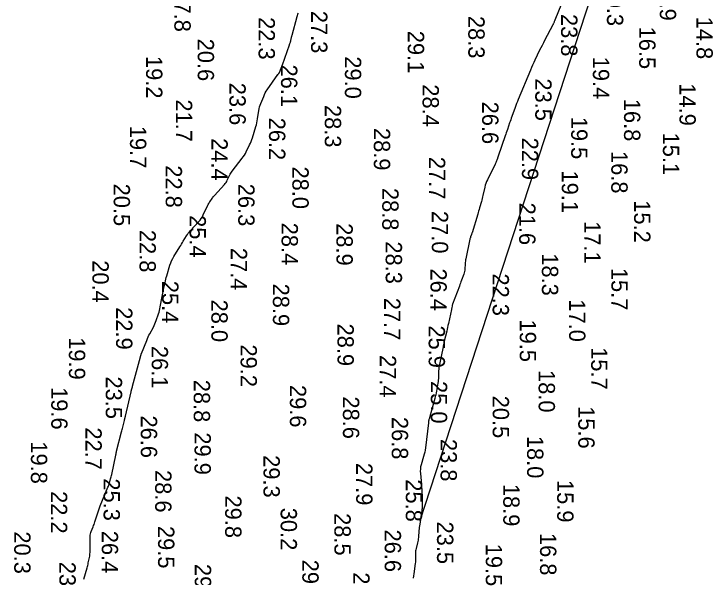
# Model space of a CAD drawing. Extents: x 1178573 to 1187098, y 693282 to 751751.
# Drawn here: x 1178579 to 1179114, y 717678 to 718109 of the extents above; entities that cross this region are included whole.
import ezdxf

# ---------------------------------------------------------------- set-up
doc = ezdxf.new("R2010")
doc.units = 0
for name, color, linetype in [('G-ANNO-PATT', 7, 'Continuous'), ('V-HYDS-MAJR', 7, 'Continuous'), ('V-HYDS-SOUN', 7, 'Continuous')]:
    doc.layers.add(name, color=color, linetype=linetype)

msp = doc.modelspace()

# ---------------------------------------------------------------- linework, layer by layer
at = {"layer": 'G-ANNO-PATT'}
msp.add_line((1178890.09, 717721.65), (1179089.95, 718334.23), dxfattribs=at)
msp.add_lwpolyline([(1178998.18, 718116.98), (1178993.14, 718104.59), (1178993.09, 718104.45), (1178993.04, 718104.32), (1178992.99, 718104.19), (1178992.94, 718104.05), (1178992.76, 718103.52), (1178992.72, 718103.38), (1178992.67, 718103.25), (1178992.61, 718103.12), (1178992.56, 718102.99), (1178992.1, 718101.97), (1178992.01, 718101.76), (1178991.91, 718101.55), (1178991.8, 718101.34), (1178991.7, 718101.14), (1178985.33, 718089.03), (1178984.36, 718087.17), (1178983.41, 718085.31), (1178982.47, 718083.44), (1178981.54, 718081.56), (1178977.87, 718074.03), (1178976.96, 718072.14), (1178976.09, 718070.24), (1178975.25, 718068.33), (1178974.43, 718066.4), (1178965.15, 718043.89), (1178964.53, 718042.36), (1178963.92, 718040.82), (1178963.33, 718039.27), (1178962.75, 718037.72), (1178960.24, 718030.84), (1178959.79, 718029.61), (1178959.35, 718028.38), (1178958.92, 718027.15), (1178958.49, 718025.91), (1178956.8, 718020.96), (1178956.38, 718019.73), (1178955.95, 718018.49), (1178955.53, 718017.25), (1178955.11, 718016.01), (1178949.82, 718000.54), (1178949.76, 718000.34), (1178949.69, 718000.15), (1178949.62, 717999.95), (1178949.55, 717999.76), (1178949.28, 717998.98), (1178949.21, 717998.79), (1178949.14, 717998.59), (1178949.07, 717998.4), (1178949, 717998.21), (1178948.19, 717996.1), (1178948.03, 717995.69), (1178947.86, 717995.28), (1178947.67, 717994.88), (1178947.48, 717994.48), (1178941.47, 717982.4), (1178940.85, 717981.05), (1178940.32, 717979.67), (1178939.87, 717978.26), (1178939.51, 717976.82), (1178938.13, 717970.53), (1178937.85, 717969.31), (1178937.55, 717968.1), (1178937.24, 717966.9), (1178936.9, 717965.69), (1178935.51, 717960.9), (1178935.16, 717959.7), (1178934.81, 717958.51), (1178934.45, 717957.31), (1178934.09, 717956.12), (1178929.75, 717941.91), (1178929.64, 717941.57), (1178929.53, 717941.23), (1178929.42, 717940.89), (1178929.3, 717940.55), (1178928.68, 717938.83), (1178928.63, 717938.67), (1178928.58, 717938.51), (1178928.52, 717938.36), (1178928.47, 717938.2), (1178928.27, 717937.57), (1178928.22, 717937.41), (1178928.18, 717937.25), (1178928.14, 717937.09), (1178928.1, 717936.93), (1178924.99, 717922.01), (1178924.8, 717921.04), (1178924.66, 717920.06), (1178924.55, 717919.08), (1178924.49, 717918.09), (1178924.3, 717914.13), (1178924.22, 717913.15), (1178924.06, 717912.18), (1178923.82, 717911.23), (1178923.51, 717910.3), (1178921.69, 717905.5), (1178921.27, 717904.39), (1178920.85, 717903.28), (1178920.44, 717902.17), (1178920.02, 717901.06), (1178914.84, 717887.22), (1178914.73, 717886.88), (1178914.62, 717886.54), (1178914.54, 717886.2), (1178914.47, 717885.85), (1178914.21, 717884.45), (1178914.15, 717884.1), (1178914.08, 717883.75), (1178914.01, 717883.4), (1178913.94, 717883.05), (1178911.62, 717872.32), (1178911.31, 717870.91), (1178911, 717869.5), (1178910.68, 717868.09), (1178910.35, 717866.68), (1178908.52, 717858.94), (1178908.44, 717858.58), (1178908.36, 717858.22), (1178908.28, 717857.86), (1178908.2, 717857.5), (1178907.89, 717856.06), (1178907.81, 717855.7), (1178907.73, 717855.34), (1178907.66, 717854.98), (1178907.58, 717854.62), (1178904.73, 717841.06), (1178904.51, 717839.89), (1178904.34, 717838.7), (1178904.23, 717837.51), (1178904.18, 717836.31), (1178904.08, 717831.52), (1178904.03, 717830.32), (1178903.93, 717829.13), (1178903.79, 717827.94), (1178903.59, 717826.76), (1178902.47, 717820.68), (1178902.2, 717819.28), (1178901.9, 717817.88), (1178901.57, 717816.49), (1178901.21, 717815.1), (1178897.48, 717801.19), (1178897.4, 717800.91), (1178897.32, 717800.64), (1178897.23, 717800.37), (1178897.14, 717800.09), (1178896.69, 717798.85), (1178896.63, 717798.66), (1178896.58, 717798.46), (1178896.55, 717798.26), (1178896.52, 717798.06), (1178896.46, 717797.26), (1178896.45, 717797.05), (1178896.43, 717796.85), (1178896.41, 717796.65), (1178896.38, 717796.45), (1178894.04, 717777.28), (1178893.8, 717775.62), (1178893.5, 717773.98), (1178893.13, 717772.35), (1178892.69, 717770.74), (1178890.8, 717764.31), (1178890.4, 717762.7), (1178890.17, 717761.07), (1178890.09, 717759.42), (1178890.16, 717757.76), (1178890.96, 717749.32), (1178891.06, 717748.14), (1178891.15, 717746.96), (1178891.24, 717745.78), (1178891.31, 717744.6), (1178891.61, 717739.17), (1178891.65, 717738.34), (1178891.67, 717737.51), (1178891.67, 717736.68), (1178891.66, 717735.85), (1178891.57, 717732.53), (1178891.54, 717731.7), (1178891.48, 717730.87), (1178891.39, 717730.05), (1178891.27, 717729.23), (1178890.09, 717721.65)], dxfattribs=at)
at = {"layer": 'V-HYDS-MAJR'}
for points in [[(1178998.18, 718116.98), (1178993.14, 718104.59), (1178993.09, 718104.45), (1178993.04, 718104.32), (1178992.99, 718104.19), (1178992.94, 718104.05), (1178992.76, 718103.52), (1178992.72, 718103.38), (1178992.67, 718103.25), (1178992.61, 718103.12), (1178992.56, 718102.99), (1178992.1, 718101.97), (1178992.01, 718101.76), (1178991.91, 718101.55), (1178991.8, 718101.34), (1178991.7, 718101.14), (1178985.33, 718089.03), (1178984.36, 718087.17), (1178983.41, 718085.31), (1178982.47, 718083.44), (1178981.54, 718081.56), (1178977.87, 718074.03), (1178976.96, 718072.14), (1178976.09, 718070.24), (1178975.25, 718068.33), (1178974.43, 718066.4), (1178965.15, 718043.89), (1178964.53, 718042.36), (1178963.92, 718040.82), (1178963.33, 718039.27), (1178962.75, 718037.72), (1178960.24, 718030.84), (1178959.79, 718029.61), (1178959.35, 718028.38), (1178958.92, 718027.15), (1178958.49, 718025.91), (1178956.8, 718020.96), (1178956.38, 718019.73), (1178955.95, 718018.49), (1178955.53, 718017.25), (1178955.11, 718016.01), (1178949.82, 718000.54), (1178949.76, 718000.34), (1178949.69, 718000.15), (1178949.62, 717999.95), (1178949.55, 717999.76), (1178949.28, 717998.98), (1178949.21, 717998.79), (1178949.14, 717998.59), (1178949.07, 717998.4), (1178949, 717998.21), (1178948.19, 717996.1), (1178948.03, 717995.69), (1178947.86, 717995.28), (1178947.67, 717994.88), (1178947.48, 717994.48), (1178941.47, 717982.4), (1178940.85, 717981.05), (1178940.32, 717979.67), (1178939.87, 717978.26), (1178939.51, 717976.82), (1178938.13, 717970.53), (1178937.85, 717969.31), (1178937.55, 717968.1), (1178937.24, 717966.9), (1178936.9, 717965.69), (1178935.51, 717960.9), (1178935.16, 717959.7), (1178934.81, 717958.51), (1178934.45, 717957.31), (1178934.09, 717956.12), (1178929.75, 717941.91), (1178929.64, 717941.57), (1178929.53, 717941.23), (1178929.42, 717940.89), (1178929.3, 717940.55), (1178928.68, 717938.83), (1178928.63, 717938.67), (1178928.58, 717938.51), (1178928.52, 717938.36), (1178928.47, 717938.2), (1178928.27, 717937.57), (1178928.22, 717937.41), (1178928.18, 717937.25), (1178928.14, 717937.09), (1178928.1, 717936.93), (1178924.99, 717922.01), (1178924.8, 717921.04), (1178924.66, 717920.06), (1178924.55, 717919.08), (1178924.49, 717918.09), (1178924.3, 717914.13), (1178924.22, 717913.15), (1178924.06, 717912.18), (1178923.82, 717911.23), (1178923.51, 717910.3), (1178921.69, 717905.5), (1178921.27, 717904.39), (1178920.85, 717903.28), (1178920.44, 717902.17), (1178920.02, 717901.06), (1178914.84, 717887.22), (1178914.73, 717886.88), (1178914.62, 717886.54), (1178914.54, 717886.2), (1178914.47, 717885.85), (1178914.21, 717884.45), (1178914.15, 717884.1), (1178914.08, 717883.75), (1178914.01, 717883.4), (1178913.94, 717883.05), (1178911.62, 717872.32), (1178911.31, 717870.91), (1178911, 717869.5), (1178910.68, 717868.09), (1178910.35, 717866.68), (1178908.52, 717858.94), (1178908.44, 717858.58), (1178908.36, 717858.22), (1178908.28, 717857.86), (1178908.2, 717857.5), (1178907.89, 717856.06), (1178907.81, 717855.7), (1178907.73, 717855.34), (1178907.66, 717854.98), (1178907.58, 717854.62), (1178904.73, 717841.06), (1178904.51, 717839.89), (1178904.34, 717838.7), (1178904.23, 717837.51), (1178904.18, 717836.31), (1178904.08, 717831.52), (1178904.03, 717830.32), (1178903.93, 717829.13), (1178903.79, 717827.94), (1178903.59, 717826.76), (1178902.47, 717820.68), (1178902.2, 717819.28), (1178901.9, 717817.88), (1178901.57, 717816.49), (1178901.21, 717815.1), (1178897.48, 717801.19), (1178897.4, 717800.91), (1178897.32, 717800.64), (1178897.23, 717800.37), (1178897.14, 717800.09), (1178896.69, 717798.85), (1178896.63, 717798.66), (1178896.58, 717798.46), (1178896.55, 717798.26), (1178896.52, 717798.06), (1178896.46, 717797.26), (1178896.45, 717797.05), (1178896.43, 717796.85), (1178896.41, 717796.65), (1178896.38, 717796.45), (1178894.04, 717777.28), (1178893.8, 717775.62), (1178893.5, 717773.98), (1178893.13, 717772.35), (1178892.69, 717770.74), (1178890.8, 717764.31), (1178890.4, 717762.7), (1178890.17, 717761.07), (1178890.09, 717759.42), (1178890.16, 717757.76), (1178890.96, 717749.32), (1178891.06, 717748.14), (1178891.15, 717746.96), (1178891.24, 717745.78), (1178891.31, 717744.6), (1178891.61, 717739.17), (1178891.65, 717738.34), (1178891.67, 717737.51), (1178891.67, 717736.68), (1178891.66, 717735.85), (1178891.57, 717732.53), (1178891.54, 717731.7), (1178891.48, 717730.87), (1178891.39, 717730.05), (1178891.27, 717729.23), (1178889.65, 717718.86), (1178889.47, 717717.64), (1178889.31, 717716.41), (1178889.18, 717715.18), (1178889.06, 717713.95), (1178888.62, 717708.64), (1178888.51, 717707.59), (1178888.36, 717706.55), (1178888.16, 717705.52), (1178887.92, 717704.5), (1178886.83, 717700.25), (1178886.62, 717699.31), (1178886.47, 717698.35), (1178886.39, 717697.4), (1178886.37, 717696.43), (1178886.44, 717692.55), (1178886.44, 717691.58), (1178886.4, 717690.61), (1178886.32, 717689.65), (1178886.2, 717688.68), (1178885.11, 717680.89), (1178884.89, 717679.28), (1178884.68, 717677.65)], [(1178632.41, 717676.74), (1178634.88, 717685.4), (1178635.15, 717686.36), (1178635.39, 717687.32), (1178635.62, 717688.28), (1178635.83, 717689.25), (1178636.87, 717694.33), (1178636.94, 717694.7), (1178637, 717695.07), (1178637.05, 717695.45), (1178637.08, 717695.83), (1178637.2, 717697.35), (1178637.22, 717697.72), (1178637.24, 717698.1), (1178637.25, 717698.48), (1178637.25, 717698.86), (1178637.22, 717709.57), (1178637.26, 717710.53), (1178637.4, 717711.48), (1178637.64, 717712.4), (1178637.97, 717713.31), (1178639.48, 717716.9), (1178639.85, 717717.8), (1178640.2, 717718.71), (1178640.54, 717719.62), (1178640.85, 717720.54), (1178644.73, 717732.19), (1178644.75, 717732.25), (1178644.77, 717732.31), (1178644.79, 717732.37), (1178644.82, 717732.43), (1178644.9, 717732.66), (1178644.92, 717732.72), (1178644.94, 717732.78), (1178644.97, 717732.84), (1178644.99, 717732.9), (1178650.89, 717747.08), (1178651.2, 717747.87), (1178651.5, 717748.66), (1178651.77, 717749.47), (1178652.01, 717750.29), (1178652.94, 717753.56), (1178653.17, 717754.38), (1178653.38, 717755.2), (1178653.58, 717756.03), (1178653.76, 717756.86), (1178656.92, 717771.76), (1178656.96, 717771.97), (1178657.01, 717772.18), (1178657.05, 717772.39), (1178657.09, 717772.6), (1178657.28, 717773.7), (1178657.3, 717773.78), (1178657.32, 717773.87), (1178657.34, 717773.96), (1178657.36, 717774.04), (1178657.44, 717774.38), (1178657.46, 717774.47), (1178657.48, 717774.55), (1178657.5, 717774.64), (1178657.52, 717774.72), (1178661.26, 717789.43), (1178661.49, 717790.32), (1178661.71, 717791.21), (1178661.94, 717792.1), (1178662.17, 717792.98), (1178663.51, 717798.21), (1178663.53, 717798.26), (1178663.54, 717798.31), (1178663.55, 717798.36), (1178663.56, 717798.41), (1178663.61, 717798.61), (1178663.62, 717798.66), (1178663.63, 717798.71), (1178663.64, 717798.76), (1178663.66, 717798.81), (1178664.03, 717800.41), (1178664.1, 717800.7), (1178664.16, 717800.98), (1178664.23, 717801.26), (1178664.29, 717801.55), (1178668.53, 717820.09), (1178668.62, 717820.47), (1178668.71, 717820.84), (1178668.82, 717821.22), (1178668.92, 717821.59), (1178669.37, 717823.08), (1178669.47, 717823.45), (1178669.58, 717823.83), (1178669.69, 717824.2), (1178669.79, 717824.58), (1178675.82, 717847.05), (1178675.87, 717847.25), (1178675.93, 717847.46), (1178675.98, 717847.66), (1178676.03, 717847.87), (1178676.25, 717848.69), (1178676.31, 717848.9), (1178676.37, 717849.1), (1178676.44, 717849.3), (1178676.52, 717849.5), (1178680.55, 717859.55), (1178681.09, 717860.85), (1178681.67, 717862.14), (1178682.29, 717863.4), (1178682.93, 717864.65), (1178685.64, 717869.7), (1178686.26, 717870.91), (1178686.83, 717872.14), (1178687.35, 717873.4), (1178687.81, 717874.67), (1178689.59, 717879.83), (1178690, 717881.12), (1178690.37, 717882.43), (1178690.68, 717883.75), (1178690.95, 717885.08), (1178692.36, 717893.06), (1178692.6, 717894.39), (1178692.86, 717895.73), (1178693.13, 717897.05), (1178693.41, 717898.38), (1178694.58, 717903.68), (1178694.89, 717905), (1178695.22, 717906.32), (1178695.57, 717907.63), (1178695.94, 717908.93), (1178698.35, 717917.05), (1178698.93, 717918.81), (1178699.63, 717920.52), (1178700.45, 717922.17), (1178701.38, 717923.78), (1178706.01, 717931.19), (1178706.66, 717932.23), (1178707.3, 717933.28), (1178707.93, 717934.33), (1178708.57, 717935.38), (1178711.08, 717939.6), (1178711.74, 717940.63), (1178712.44, 717941.62), (1178713.21, 717942.58), (1178714.02, 717943.49), (1178720.33, 717950.18), (1178721.39, 717951.4), (1178722.34, 717952.69), (1178723.18, 717954.05), (1178723.91, 717955.48), (1178727.32, 717962.91), (1178727.66, 717963.6), (1178728.02, 717964.28), (1178728.42, 717964.93), (1178728.85, 717965.57), (1178730.61, 717968.1), (1178731.06, 717968.72), (1178731.53, 717969.33), (1178732.02, 717969.92), (1178732.52, 717970.5), (1178740.12, 717978.83), (1178740.76, 717979.58), (1178741.33, 717980.38), (1178741.84, 717981.22), (1178742.29, 717982.11), (1178743.96, 717985.72), (1178744.4, 717986.61), (1178744.89, 717987.47), (1178745.43, 717988.29), (1178746.01, 717989.09), (1178753.69, 717998.93), (1178754.56, 718000.1), (1178755.37, 718001.32), (1178756.12, 718002.58), (1178756.8, 718003.87), (1178759.41, 718009.13), (1178760.03, 718010.46), (1178760.6, 718011.8), (1178761.1, 718013.18), (1178761.55, 718014.57), (1178764.12, 718023.13), (1178764.53, 718024.61), (1178764.9, 718026.1), (1178765.21, 718027.6), (1178765.48, 718029.11), (1178766.45, 718035.36), (1178766.72, 718036.78), (1178767.06, 718038.18), (1178767.49, 718039.55), (1178768, 718040.91), (1178770.18, 718046.28), (1178770.76, 718047.6), (1178771.42, 718048.89), (1178772.14, 718050.13), (1178772.93, 718051.34), (1178781.03, 718062.9), (1178781.13, 718063.04), (1178781.23, 718063.18), (1178781.34, 718063.31), (1178781.44, 718063.44), (1178781.88, 718063.96), (1178781.98, 718064.09), (1178782.07, 718064.23), (1178782.15, 718064.38), (1178782.22, 718064.53), (1178783.55, 718067.98), (1178783.79, 718068.61), (1178784.03, 718069.24), (1178784.26, 718069.88), (1178784.49, 718070.51), (1178789.84, 718085.6), (1178789.94, 718085.88), (1178790.05, 718086.17), (1178790.15, 718086.45), (1178790.26, 718086.74), (1178790.7, 718087.87), (1178790.8, 718088.16), (1178790.89, 718088.45), (1178790.97, 718088.74), (1178791.03, 718089.03), (1178791.45, 718091.26), (1178791.54, 718091.72), (1178791.65, 718092.19), (1178791.76, 718092.65), (1178791.89, 718093.12), (1178795.87, 718107.35), (1178796.14, 718108.23), (1178796.44, 718109.1), (1178796.77, 718109.96)]]:
    msp.add_lwpolyline(points, dxfattribs=at)

# ---------------------------------------------------------------- texts
at = {"layer": 'V-HYDS-SOUN'}
for s, p in [('20.3 ', (1179033.1, 718132.63)), ('16.9 ', (1179073.57, 718136.7)), ('17.8 ', (1178701.75, 718128.17)), ('27.3 ', (1178806.46, 718111.76)), ('22.3 ', (1178766.24, 718106.94)), ('28.3 ', (1178926.9, 718107.86)), ('23.8 ', (1178997.97, 718109.34)), ('14.8 ', (1179101.65, 718107.24)), ('29.1 ', (1178880.56, 718096.47)), ('16.5 ', (1179057.78, 718099.67)), ('20.6 ', (1178719.62, 718090.44)), ('19.2 ', (1178680.07, 718077.18)), ('29.0 ', (1178832.38, 718076.96)), ('19.4 ', (1179022.31, 718076.64)), ('26.1 ', (1178783.44, 718070.65)), ('23.5 ', (1178978.19, 718060.04)), ('23.6 ', (1178743.9, 718056.71)), ('28.4 ', (1178891.86, 718055.51)), ('14.9 ', (1179088.62, 718056.25)), ('21.7 ', (1178702.95, 718043.95)), ('26.6 ', (1178937.5, 718042.24)), ('16.8 ', (1179046.17, 718044.41)), ('28.3 ', (1178816.99, 718039.68)), ('26.2 ', (1178774.24, 718029.97)), ('19.5 ', (1179005.68, 718030.67)), ('19.7 ', (1178667.75, 718023.77)), ('28.9 ', (1178854.54, 718022.1)), ('15.1 ', (1179075.96, 718018.55)), ('24.4 ', (1178730.12, 718014.3)), ('22.9 ', (1178967.99, 718014.72)), ('27.7 ', (1178896.75, 718000.02)), ('16.8 ', (1179036.43, 718004.45)), ('22.8 ', (1178695.12, 717993.52)), ('28.0 ', (1178792.13, 717992.61)), ('19.1 ', (1178998.5, 717989.54)), ('20.5 ', (1178655.26, 717979.49)), ('26.3 ', (1178750.66, 717979.38)), ('28.8 ', (1178861, 717976.2)), ('21.6 ', (1178965.85, 717964.98)), ('15.2 ', (1179053.89, 717966.75)), ('27.0 ', (1178898.95, 717958.59)), ('25.4 ', (1178713.42, 717955.41)), ('28.4 ', (1178783.89, 717949.6)), ('28.9 ', (1178825.9, 717949.23)), ('17.1 ', (1179015.69, 717950.8)), ('22.8 ', (1178675.04, 717944.08)), ('28.3 ', (1178863.61, 717935.29)), ('27.4 ', (1178744.98, 717930.31)), ('18.3 ', (1178983.27, 717926.17)), ('20.4 ', (1178638.98, 717920.83)), ('26.4 ', (1178897.87, 717914.56)), ('15.7 ', (1179036.48, 717915.04)), ('22.3 ', (1178945.54, 717910.75)), ('25.4 ', (1178692.39, 717905.11)), ('28.9 ', (1178777.24, 717902.97)), ('27.7 ', (1178862.37, 717892.11)), ('28.0 ', (1178730.08, 717890.74)), ('17.0 ', (1179004.07, 717890.94)), ('22.9 ', (1178657.1, 717884.93)), ('28.9 ', (1178826.68, 717872.39)), ('25.9 ', (1178896.53, 717870.98)), ('19.5 ', (1178966.31, 717875.52)), ('19.9 ', (1178620.97, 717861.96)), ('26.1 ', (1178684.4, 717855.26)), ('29.2 ', (1178752.48, 717856.41)), ('15.7 ', (1179021, 717854.32)), ('27.4 ', (1178859.12, 717848.29)), ('18.0 ', (1178980.77, 717836.84)), ('23.5 ', (1178649.22, 717831.92)), ('28.8 ', (1178716.58, 717829.38)), ('25.0 ', (1178898.19, 717828.41)), ('19.6 ', (1178607.45, 717823.74)), ('29.6 ', (1178790.22, 717825.38)), ('20.5 ', (1178945.58, 717817.16)), ('28.6 ', (1178830.87, 717816.65)), ('15.6 ', (1179011.15, 717809.17)), ('26.6 ', (1178676.05, 717802.05)), ('26.8 ', (1178868.28, 717800.94)), ('22.7 ', (1178633.6, 717792.93)), ('29.9 ', (1178717.17, 717789.13)), ('18.0 ', (1178971.92, 717786.45)), ('19.8 ', (1178591.87, 717782.24)), ('23.8 ', (1178905.65, 717784.07)), ('29.3 ', (1178770.01, 717771.67)), ('27.9 ', (1178840.99, 717765.77)), ('28.6 ', (1178687.04, 717760.29)), ('25.3 ', (1178647.54, 717753.92)), ('25.8 ', (1178879.04, 717753.2)), ('18.9 ', (1178953.68, 717749.72)), ('15.9 ', (1178994.99, 717752.68)), ('22.2 ', (1178607.18, 717744.18)), ('29.8 ', (1178740.66, 717740.8)), ('30.2 ', (1178783.16, 717731.41)), ('28.5 ', (1178824.32, 717727.33)), ('23.5 ', (1178902.93, 717720.86)), ('29.5 ', (1178689.25, 717717.49)), ('20.3 ', (1178579.07, 717713.34)), ('26.4 ', (1178646.13, 717713.78)), ('26.6 ', (1178862.86, 717714.75)), ('16.8 ', (1178981.83, 717712.13)), ('19.5 ', (1178940.3, 717703.9)), ('23.7 ', (1178613.68, 717690.08)), ('29.6 ', (1178717.42, 717688.4)), ('29.2 ', (1178799.76, 717691.68)), ('27.8 ', (1178838.79, 717682.04))]:
    msp.add_text(s, height=12.5, rotation=270, dxfattribs=at).set_placement(p)

doc.saveas('drawing.dxf')
